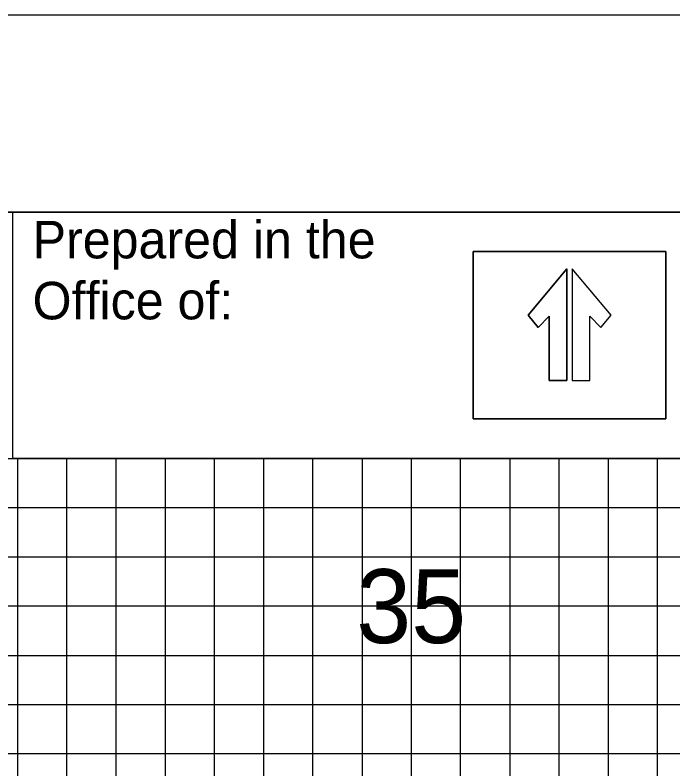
# Model space of a CAD drawing. Extents: x -7 to 162, y -2 to 217.
# Drawn here: x 110.98 to 117.66, y 209.35 to 217 of the extents above; entities that cross this region are included whole.
import ezdxf

# ---------------------------------------------------------------- set-up
doc = ezdxf.new("R2010")
doc.units = 0
for name, color, linetype in [('Exist Cross Section Cell', 7, 'Continuous'), ('Prop CMT Guardrail Widen Shoulder', 7, 'Continuous'), ('Prop CMT Pvmt Course 3', 7, 'Continuous'), ('Prop CMT Shld Paved Course 1', 7, 'Continuous'), ('Prop CMT Shld Paved Course 2', 7, 'Continuous'), ('Prop CMT Shld Paved Course 3', 7, 'Continuous'), ('Prop CMT Slope Grass', 7, 'Continuous'), ('Prop CMT Subgrade Earthwork', 7, 'Continuous'), ('Prop XS Earthwork Shape', 7, 'Continuous'), ('Scratch_Level_0', 7, 'Continuous'), ('Scratch_Level_3', 7, 'Continuous')]:
    doc.layers.add(name, color=color, linetype=linetype)

msp = doc.modelspace()

# ---------------------------------------------------------------- linework, layer by layer
at = {"layer": 'Prop CMT Guardrail Widen Shoulder'}
msp.add_lwpolyline([(110.9512, 215), (130, 215), (130, 212.5), (110.9512, 212.5)], close=True, dxfattribs=at)
at = {"layer": 'Prop CMT Pvmt Course 3'}
msp.add_lwpolyline([(-6.7, 107.5), (161.65, 107.5), (161.65, 217), (-6.7, 217)], close=True, dxfattribs=at)
at = {"layer": 'Prop CMT Shld Paved Course 1'}
msp.add_line((0, 212), (160, 212), dxfattribs=at)
for points in [[(0, 211.5), (135, 211.5), (160, 211.5)], [(160, 211), (0, 211)], [(0, 210.5), (160, 210.5)], [(160, 209.5), (0, 209.5)]]:
    msp.add_lwpolyline(points, dxfattribs=at)
at = {"layer": 'Prop CMT Shld Paved Course 2'}
msp.add_lwpolyline([(160, 215), (0, 215), (0, 110), (160, 110)], close=True, dxfattribs=at)
at = {"layer": 'Prop CMT Shld Paved Course 3'}
for points in [[(110, 110), (110.5, 110), (110.5, 215), (111, 215)], [(111.5, 215), (112, 215)], [(113, 215), (113.5, 215)], [(114, 215), (114.5, 215)], [(115.5, 215), (116, 215)], [(116.5, 215), (117, 215)], [(111, 212.5), (111, 110)], [(111, 110), (111.5, 110), (111.5, 212.5)], [(112, 212.5), (112, 110)], [(112.5, 110), (113, 110), (113, 212.5)], [(113.5, 212.5), (113.5, 110)], [(113.5, 110), (114, 110), (114, 212.5)], [(114.5, 212.5), (114.5, 110)], [(115, 110), (115.5, 110), (115.5, 212.5)], [(116, 212.5), (116, 110)], [(116, 110), (116.5, 110), (116.5, 212.5)], [(117, 212.5), (117, 110)]]:
    msp.add_lwpolyline(points, dxfattribs=at)
at = {"layer": 'Prop CMT Slope Grass'}
for points in [[(72.5, 110), (77.5, 110), (77.5, 215), (82.5, 215), (82.5, 110), (87.5, 110), (87.5, 215), (92.5, 215), (92.5, 110), (97.5, 110), (97.5, 215), (102.5, 215), (102.5, 110), (107.5, 110), (107.5, 215), (112.5, 215)], [(117.5, 215), (122.5, 215)], [(0, 212.5), (137.5, 212.5)], [(112.5, 212.5), (112.5, 110), (117.5, 110), (117.5, 212.5)]]:
    msp.add_lwpolyline(points, dxfattribs=at)
at = {"layer": 'Prop CMT Subgrade Earthwork'}
msp.add_lwpolyline([(-5.4, 109.5), (161.2, 109.5), (161.2, 215), (-5.4, 215)], close=True, dxfattribs=at)
at = {"layer": 'Prop XS Earthwork Shape'}
for points in [[(117.584, 214.5995), (115.6266, 214.5995), (115.6266, 212.9005), (117.584, 212.9005), (117.584, 214.5995)], [(116.5788, 214.4257), (116.5788, 213.2897), (116.3999, 213.2897), (116.3999, 213.945), (116.2891, 213.8276), (116.1849, 213.9521), (116.5788, 214.4257)], [(116.1849, 213.9521), (116.2891, 213.8276), (116.3999, 213.945), (116.3999, 213.2897), (116.5788, 213.2897), (116.5788, 214.4257), (116.1849, 213.9521)], [(116.6339, 214.4257), (116.6339, 213.2897), (116.8129, 213.2897), (116.8129, 213.945), (116.9237, 213.8276), (117.0279, 213.9521), (116.6339, 214.4257)]]:
    msp.add_lwpolyline(points, dxfattribs=at)
for points in [[(115.6266, 214.5995), (117.584, 214.5995), (117.584, 212.9005), (115.6266, 212.9005)], [(116.6339, 214.4257), (116.6339, 213.2897), (116.8129, 213.2897), (116.8129, 213.945), (116.9237, 213.8276), (117.0279, 213.9521)]]:
    msp.add_lwpolyline(points, close=True, dxfattribs=at)
at = {"layer": 'Scratch_Level_3'}
for p, q in [((115, 215), (110, 215)), ((115, 110), (115, 212.5))]:
    msp.add_line(p, q, dxfattribs=at)
msp.add_lwpolyline([(0, 210), (160, 210)], dxfattribs=at)

# ---------------------------------------------------------------- texts
at = {"layer": 'Exist Cross Section Cell'}
msp.add_text('35', height=0.75, dxfattribs=at).set_placement((114.4408, 210.625))
at = {"layer": 'Scratch_Level_0'}
for s, height, p in [('Prepared in the ', 0.380976, (111.1533, 214.5302)), ('Office of:', 0.38098, (111.1533, 213.9112))]:
    msp.add_text(s, height=height, rotation=360, dxfattribs=at).set_placement(p)

doc.saveas('drawing.dxf')
